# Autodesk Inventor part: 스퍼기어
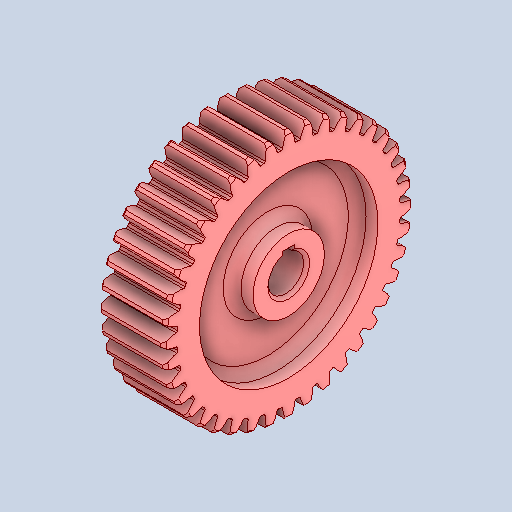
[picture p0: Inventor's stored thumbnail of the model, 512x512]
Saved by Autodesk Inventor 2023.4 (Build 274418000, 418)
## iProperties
Created: 2024-11
Part Number: 스퍼기어
Material: 강철, 탄소
Document SubType Name: Modeling
Designer: EDU
Density: 7.85 g/cm^3
Appearance: 기본값
Author: jhkim
Sending System: Autodesk Inventor 2025
Preprocessor: ST-DEVELOPER v20
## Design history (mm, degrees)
feature "솔리드1"
node "솔리드2"
